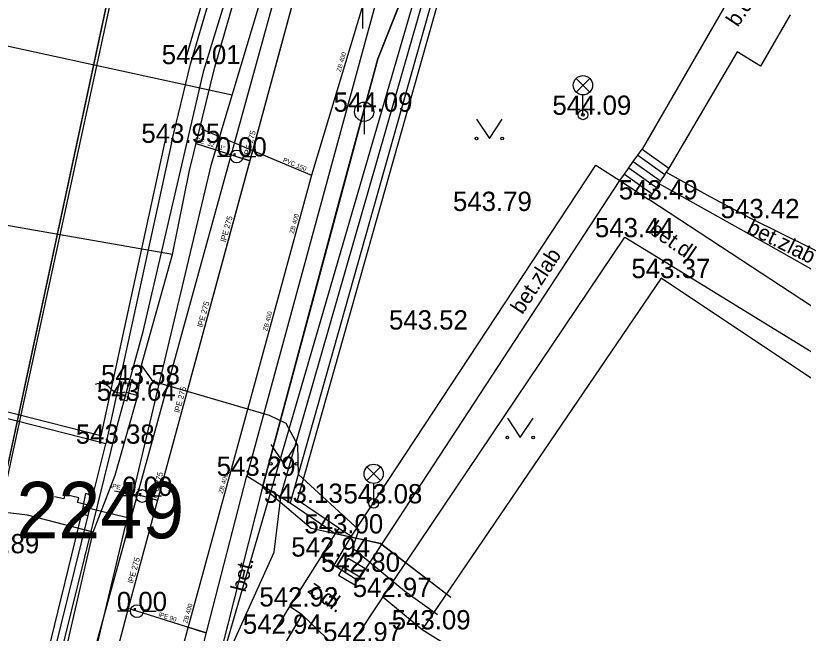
# Model space of a CAD drawing. Extents: x -669393 to -668650, y -1126925 to -1126294.
# Drawn here: x -668961.14 to -668930.51, y -1126607.07 to -1126583.06 of the extents above; entities that cross this region are included whole.
import ezdxf

# ---------------------------------------------------------------- set-up
doc = ezdxf.new("R2010")
doc.units = 0
for name, color, linetype in [('G_Bod_tecka', 7, 'Continuous'), ('G_Bod_vyska', 7, 'Continuous'), ('G_Budovy_Objekty', 7, 'Continuous'), ('G_Cesty_Schody', 7, 'Continuous'), ('G_Objekty_technicke', 7, 'Continuous'), ('G_Plochy_zpevnene', 7, 'Continuous'), ('G_Ploty', 7, 'Continuous'), ('G_Ploty_vstupy', 7, 'Continuous'), ('G_Popisy_povrchu', 7, 'Continuous'), ('G_Site-kanalizace', 7, 'Continuous'), ('G_Site-Rozvadece', 7, 'Continuous'), ('G_Site-vodovod', 7, 'Continuous'), ('G_Z_ELsilove_nadz_kotovane', 7, 'Continuous'), ('G_Z_ELsilove_podz_kotovane', 7, 'Continuous'), ('G_Z_KANAL_podz_kotovane', 7, 'Continuous'), ('G_Z_PLYNY_podz_geodeticky', 7, 'Continuous'), ('G_Z_SPOJE_podz_geodeticky', 7, 'Continuous'), ('G_Z_SPOJE_podz_kotovane', 7, 'Continuous'), ('G_Z_SPOJE_podz_priblizne', 7, 'Continuous'), ('G_Z_SPOJE_podz_zahozene', 7, 'Continuous'), ('G_Z_VODA_podz_kotovane', 7, 'Continuous'), ('G_Zelen-Znacky', 7, 'Continuous'), ('Vrstva 11', 7, 'Continuous'), ('Vrstva 12', 7, 'Continuous'), ('Vrstva 13', 7, 'Continuous'), ('Vrstva 26', 7, 'Continuous'), ('Vrstva 3', 7, 'Continuous'), ('Vrstva 4', 7, 'Continuous'), ('Vrstva 5', 7, 'Continuous'), ('Vrstva 6', 7, 'Continuous')]:
    doc.layers.add(name, color=color, linetype=linetype)

msp = doc.modelspace()

# ---------------------------------------------------------------- linework, layer by layer
at = {"layer": 'G_Bod_tecka'}
for p, q in [((-668954.34, -1126584.94), (-668954.34, -1126584.94)), ((-668947.59, -1126586.79), (-668947.59, -1126586.79)), ((-668939.08, -1126586.91), (-668939.08, -1126586.91)), ((-668955.09, -1126588), (-668955.09, -1126588)), ((-668952.55, -1126588.53), (-668952.55, -1126588.53)), ((-668936.52, -1126590.2), (-668936.52, -1126590.2)), ((-668942.97, -1126590.65), (-668942.97, -1126590.65)), ((-668932.56, -1126590.93), (-668932.56, -1126590.93)), ((-668937.45, -1126591.67), (-668937.45, -1126591.67)), ((-668936.04, -1126593.26), (-668936.04, -1126593.26)), ((-668945.46, -1126595.26), (-668945.46, -1126595.26)), ((-668956.66, -1126597.39), (-668956.66, -1126597.39)), ((-668956.81, -1126598.03), (-668956.81, -1126598.03)), ((-668957.64, -1126599.7), (-668957.64, -1126599.7)), ((-668952.16, -1126600.95), (-668952.16, -1126600.95)), ((-668956.22, -1126601.73), (-668956.22, -1126601.73)), ((-668950.47, -1126602), (-668950.47, -1126602)), ((-668947.22, -1126602.02), (-668947.22, -1126602.02)), ((-668948.72, -1126603.19), (-668948.72, -1126603.19)), ((-668949.26, -1126604.09), (-668949.26, -1126604.09)), ((-668948.08, -1126604.68), (-668948.08, -1126604.68)), ((-668946.87, -1126605.66), (-668946.87, -1126605.66)), ((-668956.43, -1126606.21), (-668956.43, -1126606.21)), ((-668950.5, -1126606.03), (-668950.5, -1126606.03)), ((-668945.33, -1126606.92), (-668945.33, -1126606.92))]:
    msp.add_line(p, q, dxfattribs=at)
at = {"layer": 'G_Budovy_Objekty'}
for p, q in [((-668936.04, -1126593.26), (-668945.33, -1126606.92)), ((-668929.8, -1126597.42), (-668936.04, -1126593.26)), ((-668945.33, -1126606.92), (-668939.39, -1126610.63))]:
    msp.add_line(p, q, dxfattribs=at)
at = {"layer": 'G_Cesty_Schody'}
for p, q in [((-668947.82, -1126605.02), (-668937.65, -1126589.47)), ((-668948.76, -1126604.42), (-668947.82, -1126605.02))]:
    msp.add_line(p, q, dxfattribs=at)
for points in [[(-668937.13, -1126588.73), (-668936.95, -1126588.48)], [(-668936.95, -1126588.48), (-668936.78, -1126588.24)], [(-668936.95, -1126588.48), (-668935.9, -1126589.23)], [(-668936.78, -1126588.24), (-668935.74, -1126588.98)], [(-668937.3, -1126588.97), (-668937.13, -1126588.73)], [(-668937.13, -1126588.73), (-668936.06, -1126589.48)], [(-668937.47, -1126589.22), (-668937.3, -1126588.97)], [(-668937.3, -1126588.97), (-668936.22, -1126589.73)], [(-668935.74, -1126588.98), (-668935.84, -1126589.14)], [(-668937.65, -1126589.47), (-668937.47, -1126589.22)], [(-668937.47, -1126589.22), (-668936.39, -1126589.98)], [(-668935.9, -1126589.23), (-668936.06, -1126589.48)], [(-668935.84, -1126589.14), (-668935.9, -1126589.23)], [(-668937.65, -1126589.47), (-668936.52, -1126590.2)], [(-668936.22, -1126589.73), (-668936.39, -1126589.98)], [(-668936.13, -1126589.58), (-668936.22, -1126589.73)], [(-668936.06, -1126589.48), (-668936.13, -1126589.58)], [(-668936.39, -1126589.98), (-668936.52, -1126590.2)], [(-668946.87, -1126605.66), (-668948.02, -1126607.39)]]:
    msp.add_lwpolyline(points, dxfattribs=at)
at = {"layer": 'G_Objekty_technicke'}
for points in [[(-668939.345, -1126585.495), (-668938.815, -1126586.025)], [(-668939.345, -1126586.025), (-668938.815, -1126585.495)], [(-668939.08, -1126586.91), (-668939.08, -1126586.135)], [(-668947.485, -1126600.605), (-668946.955, -1126601.135)], [(-668947.485, -1126601.135), (-668946.955, -1126600.605)], [(-668947.22, -1126602.02), (-668947.22, -1126601.245)]]:
    msp.add_lwpolyline(points, dxfattribs=at)
for centre, radius in [((-668939.08, -1126585.76), 0.375), ((-668939.08, -1126586.91), 0.19), ((-668939.08, -1126586.91), 0.05), ((-668947.22, -1126600.87), 0.375), ((-668947.22, -1126602.02), 0.19), ((-668947.22, -1126602.02), 0.05)]:
    msp.add_circle(centre, radius, dxfattribs=at)
at = {"layer": 'G_Plochy_zpevnene'}
msp.add_line((-668953.95, -1126607.93), (-668952.16, -1126600.95), dxfattribs=at)
for points in [[(-668959.29, -1126612.12), (-668944.16, -1126557.26)], [(-668934.28, -1126572.28), (-668936.85, -1126571.84), (-668939.43, -1126571.39), (-668939.88, -1126571.34), (-668940.3, -1126571.35), (-668940.71, -1126571.41), (-668941.46, -1126571.62), (-668942.11, -1126571.92), (-668942.65, -1126572.24), (-668943.1, -1126572.57), (-668943.83, -1126573.24), (-668944.31, -1126573.8), (-668944.62, -1126574.24), (-668945, -1126574.93), (-668945.26, -1126575.64), (-668948.71, -1126588.29), (-668952.16, -1126600.95)], [(-668929.46, -1126575.58), (-668936.78, -1126588.24)], [(-668931.02, -1126583.02), (-668932.18, -1126585.02)], [(-668933.08, -1126584.46), (-668935.74, -1126588.98)], [(-668932.18, -1126585.02), (-668933.08, -1126584.46)], [(-668948.08, -1126603.3), (-668938.58, -1126588.87)], [(-668938.58, -1126588.87), (-668937.65, -1126589.47)], [(-668935.84, -1126589.14), (-668934.14, -1126590.09), (-668932.56, -1126590.93), (-668930.2, -1126592.1), (-668929.03, -1126592.7), (-668927.9, -1126593.38)], [(-668936.13, -1126589.58), (-668932.19, -1126591.78), (-668930.23, -1126592.89), (-668928.67, -1126593.82)], [(-668928.98, -1126595.14), (-668936.52, -1126590.2)], [(-668946.87, -1126605.66), (-668937.45, -1126591.67)], [(-668937.45, -1126591.67), (-668936.22, -1126592.42)], [(-668936.22, -1126592.42), (-668929.3, -1126596.67)], [(-668952.16, -1126600.95), (-668950.47, -1126602)], [(-668946.87, -1126605.66), (-668945.33, -1126606.92)], [(-668950, -1126606.35), (-668948.45, -1126607.84), (-668948.35, -1126607.87)]]:
    msp.add_lwpolyline(points, dxfattribs=at)
at = {"layer": 'G_Ploty'}
for p, q in [((-668943.35, -1126576.81), (-668950.47, -1126602)), ((-668950.18, -1126601.9), (-668943.15, -1126577)), ((-668953.45, -1126581.02), (-668954.58, -1126584.87)), ((-668954.34, -1126584.94), (-668953.21, -1126581.09)), ((-668955.34, -1126587.95), (-668957.83, -1126599.39)), ((-668955.09, -1126588), (-668957.64, -1126599.7)), ((-668957.88, -1126599.64), (-668965.58, -1126597.69)), ((-668957.83, -1126599.39), (-668965.53, -1126597.45)), ((-668957.64, -1126599.7), (-668957.88, -1126599.64)), ((-668948.57, -1126602.98), (-668950.18, -1126601.9)), ((-668950.47, -1126602), (-668948.72, -1126603.19)), ((-668958.58, -1126602.43), (-668960.88, -1126611.77)), ((-668960.64, -1126611.83), (-668958.33, -1126602.49)), ((-668948.72, -1126603.19), (-668949.26, -1126604.09)), ((-668948.57, -1126602.98), (-668948.72, -1126603.19)), ((-668948.57, -1126602.98), (-668948.08, -1126603.3)), ((-668948.76, -1126604.42), (-668948.08, -1126603.3)), ((-668949.26, -1126604.09), (-668948.76, -1126604.42)), ((-668950.5, -1126606.03), (-668951.14, -1126607.09)), ((-668950, -1126606.35), (-668950.5, -1126606.03)), ((-668950.63, -1126607.41), (-668950, -1126606.35))]:
    msp.add_line(p, q, dxfattribs=at)
at = {"layer": 'G_Ploty_vstupy'}
for p, q in [((-668955.09, -1126588), (-668954.34, -1126584.94)), ((-668958.14, -1126601.72), (-668957.64, -1126599.7)), ((-668949.26, -1126604.09), (-668950.5, -1126606.03))]:
    msp.add_line(p, q, dxfattribs=at)
at = {"layer": 'G_Site-kanalizace'}
for points in [[(-668947.66, -1126582.305), (-668947.66, -1126583.555)], [(-668947.59, -1126586.415), (-668947.59, -1126587.665)], [(-668948.403, -1126604.489), (-668947.757, -1126604.871)]]:
    msp.add_lwpolyline(points, dxfattribs=at)
msp.add_lwpolyline([(-668948.593, -1126604.811), (-668947.947, -1126605.193), (-668947.566, -1126604.547), (-668948.212, -1126604.166)], close=True, dxfattribs=at)
msp.add_circle((-668947.59, -1126586.79), 0.375, dxfattribs=at)
at = {"layer": 'G_Site-Rozvadece'}
for points in [[(-668956.95, -1126597.32), (-668957.1, -1126597.96), (-668956.81, -1126598.03), (-668956.66, -1126597.39)], [(-668958.43, -1126601.64), (-668958.58, -1126602.43), (-668958.33, -1126602.49), (-668958.14, -1126601.72)]]:
    msp.add_lwpolyline(points, close=True, dxfattribs=at)
msp.add_lwpolyline([(-668958.38, -1126602.071), (-668958.737, -1126601.981), (-668958.693, -1126601.803), (-668959.229, -1126601.671), (-668959.274, -1126601.849), (-668959.631, -1126601.761)], dxfattribs=at)
for centre, start, end in [((-668957.848, -1126597.86), 39.7092, 113.449), ((-668957.079, -1126597.221), 219.7092, 293.449)]:
    msp.add_arc(centre, 0.5, start, end, dxfattribs=at)
at = {"layer": 'G_Site-vodovod'}
for points in [[(-668952.8, -1126588.53), (-668953.3, -1126588.53)], [(-668952.3, -1126588.53), (-668951.8, -1126588.53)], [(-668956.47, -1126601.73), (-668956.97, -1126601.73)], [(-668955.97, -1126601.73), (-668955.47, -1126601.73)], [(-668956.68, -1126606.21), (-668957.18, -1126606.21)], [(-668956.18, -1126606.21), (-668955.68, -1126606.21)]]:
    msp.add_lwpolyline(points, dxfattribs=at)
for centre in [(-668952.55, -1126588.53), (-668956.22, -1126601.73), (-668956.43, -1126606.21)]:
    msp.add_circle(centre, 0.25, dxfattribs=at)
at = {"layer": 'G_Z_ELsilove_nadz_kotovane'}
msp.add_lwpolyline([(-668969.82, -1126641.84), (-668962.08, -1126603.84), (-668954.82, -1126570.41), (-668947.579, -1126533.09)], dxfattribs=at)
at = {"layer": 'G_Z_ELsilove_podz_kotovane'}
msp.add_lwpolyline([(-668986.81, -1126790.89), (-668983.74, -1126752.7), (-668981.4, -1126714.88), (-668976.88, -1126675.24), (-668969.5, -1126644.98), (-668962.32, -1126604.58), (-668954.59, -1126568.6), (-668939.06, -1126504.37)], dxfattribs=at)
at = {"layer": 'G_Z_KANAL_podz_kotovane'}
msp.add_line((-668953.93, -1126587.46), (-668949.64, -1126589.26), dxfattribs=at)
msp.add_lwpolyline([(-668947.66, -1126582.68), (-668949.64, -1126589.26), (-668954.51, -1126607.11), (-668957.21, -1126617.22), (-668960.66, -1126630.26)], dxfattribs=at)
at = {"layer": 'G_Z_PLYNY_podz_geodeticky'}
for points in [[(-668972.663, -1126674.589), (-668970.71, -1126662.16), (-668970.45, -1126660.58), (-668967.39, -1126647.2), (-668966.76, -1126644.42), (-668965.71, -1126640.04), (-668961.7, -1126623.19), (-668956.8, -1126602.57), (-668953.53, -1126588.83), (-668952.72, -1126586.15), (-668946.84, -1126566.52), (-668945.79, -1126563), (-668931.12, -1126514.78), (-668929.96, -1126511.12), (-668931.66, -1126510.6), (-668931.41, -1126509.79)], [(-668952.72, -1126586.15), (-668962.75, -1126583.97), (-668969.51, -1126582.88), (-668969.7, -1126584.58)], [(-668958.5, -1126602.16), (-668956.8, -1126602.57)]]:
    msp.add_lwpolyline(points, dxfattribs=at)
at = {"layer": 'G_Z_SPOJE_podz_geodeticky'}
for points in [[(-668965.71, -1126659.23), (-668961.42, -1126636.58), (-668943.94, -1126576.61), (-668934.24, -1126554.95), (-668916.63, -1126516.53), (-668915.06, -1126512.35), (-668913.11, -1126502.62)], [(-668955.05, -1126592.34), (-668954.38, -1126589.07), (-668953.4, -1126585.06), (-668948.63, -1126568.5)], [(-668955.05, -1126592.34), (-668964.02, -1126590.77), (-668964.1, -1126590.75)], [(-668956.25, -1126596.64), (-668955.05, -1126592.34)], [(-668956.39, -1126597.83), (-668956.25, -1126596.64)], [(-668947.8, -1126603.05), (-668950.14, -1126600.9), (-668950.17, -1126599.75), (-668950.63, -1126598.92), (-668951.27, -1126598.6), (-668955.8, -1126597.28), (-668956.25, -1126596.64)], [(-668958.13, -1126603.14), (-668957.28, -1126600.92), (-668956.39, -1126597.83)], [(-668956.86, -1126597.7), (-668956.39, -1126597.83)], [(-668958.13, -1126603.14), (-668960.68, -1126602.48), (-668961.79, -1126602.35), (-668964.35, -1126601.86), (-668966.04, -1126600.32)], [(-668963.72, -1126626.54), (-668961.18, -1126616.81), (-668960, -1126611.24), (-668958.13, -1126603.14)], [(-668947.8, -1126603.05), (-668948.04, -1126603.75), (-668946.02, -1126605.42), (-668944.74, -1126606.34)]]:
    msp.add_lwpolyline(points, dxfattribs=at)
at = {"layer": 'G_Z_SPOJE_podz_kotovane'}
for points in [[(-668974.36, -1126674.07), (-668973.06, -1126668.98), (-668971.96, -1126664.36), (-668970.68, -1126658.03), (-668969.3, -1126650.34), (-668968.2, -1126645.42), (-668967.12, -1126640.35), (-668966.32, -1126638.27), (-668965.98, -1126636.58), (-668964.19, -1126628.16), (-668961.63, -1126617.34), (-668960.75, -1126613.4), (-668957.18, -1126598.96), (-668956.18, -1126595.34), (-668953.83, -1126585.18), (-668949.97, -1126572.67), (-668944.82, -1126555.69), (-668942.42, -1126548.43), (-668938.93, -1126537.21), (-668934.92, -1126523.88)], [(-668967.21, -1126674.78), (-668966.11, -1126667.11), (-668964.1, -1126654.97), (-668963.7, -1126653.53), (-668962.9, -1126653.19), (-668960.93, -1126641.59), (-668958.61, -1126631.73), (-668954.53, -1126631.88), (-668949.06, -1126611.36), (-668952.94, -1126608.03), (-668951.09, -1126603.92), (-668950.82, -1126601.67), (-668943.9, -1126577.58), (-668943.62, -1126576.63), (-668939.63, -1126575.42), (-668938.77, -1126574.92), (-668937.37, -1126573.94), (-668936.3, -1126571.54), (-668934.65, -1126567.91), (-668933.72, -1126566.17), (-668932.96, -1126564.96)], [(-668955.05, -1126592.34), (-668954.38, -1126589.07), (-668953.4, -1126585.06), (-668948.63, -1126568.5)], [(-668955.05, -1126592.34), (-668964.02, -1126590.77), (-668964.1, -1126590.75)], [(-668956.25, -1126596.64), (-668955.05, -1126592.34)], [(-668956.39, -1126597.83), (-668956.25, -1126596.64)], [(-668947.8, -1126603.05), (-668950.14, -1126600.9), (-668950.17, -1126599.75), (-668950.63, -1126598.92), (-668951.27, -1126598.6), (-668955.8, -1126597.28), (-668956.25, -1126596.64)], [(-668958.13, -1126603.14), (-668957.28, -1126600.92), (-668956.39, -1126597.83)], [(-668956.86, -1126597.7), (-668956.39, -1126597.83)], [(-668958.13, -1126603.14), (-668960.68, -1126602.48), (-668961.79, -1126602.35), (-668964.35, -1126601.86), (-668966.04, -1126600.32)], [(-668963.72, -1126626.54), (-668961.18, -1126616.81), (-668960, -1126611.24), (-668958.13, -1126603.14)], [(-668947.8, -1126603.05), (-668948.04, -1126603.75), (-668946.02, -1126605.42), (-668944.74, -1126606.34)]]:
    msp.add_lwpolyline(points, dxfattribs=at)
at = {"layer": 'G_Z_SPOJE_podz_priblizne'}
for points in [[(-668965.71, -1126659.23), (-668961.42, -1126636.58), (-668943.94, -1126576.61), (-668934.24, -1126554.95), (-668916.63, -1126516.53), (-668915.06, -1126512.35), (-668913.11, -1126502.62)], [(-668955.05, -1126592.34), (-668954.38, -1126589.07), (-668953.4, -1126585.06), (-668948.63, -1126568.5)], [(-668955.05, -1126592.34), (-668964.02, -1126590.77), (-668964.1, -1126590.75)], [(-668956.25, -1126596.64), (-668955.05, -1126592.34)], [(-668956.39, -1126597.83), (-668956.25, -1126596.64)], [(-668947.8, -1126603.05), (-668950.14, -1126600.9), (-668950.17, -1126599.75), (-668950.63, -1126598.92), (-668951.27, -1126598.6), (-668955.8, -1126597.28), (-668956.25, -1126596.64)], [(-668958.13, -1126603.14), (-668957.28, -1126600.92), (-668956.39, -1126597.83)], [(-668956.86, -1126597.7), (-668956.39, -1126597.83)], [(-668958.13, -1126603.14), (-668960.68, -1126602.48), (-668961.79, -1126602.35), (-668964.35, -1126601.86), (-668966.04, -1126600.32)], [(-668963.72, -1126626.54), (-668961.18, -1126616.81), (-668960, -1126611.24), (-668958.13, -1126603.14)], [(-668947.8, -1126603.05), (-668948.04, -1126603.75), (-668946.02, -1126605.42), (-668944.74, -1126606.34)]]:
    msp.add_lwpolyline(points, dxfattribs=at)
at = {"layer": 'G_Z_SPOJE_podz_zahozene'}
for p, q in [((-668947.06, -1126584.73), (-668936.79, -1126558.94)), ((-668948.66, -1126590.66), (-668947.06, -1126584.73)), ((-668951.55, -1126601.39), (-668948.66, -1126590.66)), ((-668951.55, -1126601.39), (-668954.92, -1126614.72)), ((-668949.65, -1126603), (-668951.55, -1126601.39)), ((-668946.95, -1126603.59), (-668949.65, -1126603)), ((-668944.22, -1126605.68), (-668946.95, -1126603.59))]:
    msp.add_line(p, q, dxfattribs=at)
at = {"layer": 'G_Z_VODA_podz_kotovane'}
for points in [[(-668911.63, -1126458.38), (-668911.94, -1126472.87), (-668917.84, -1126504.71), (-668919.43, -1126508.14), (-668925.09, -1126520.35), (-668931.13, -1126532.07), (-668941.27, -1126553.58), (-668941.86, -1126555.28), (-668944.85, -1126563.31), (-668947.04, -1126570.29), (-668952.04, -1126588.69), (-668955.63, -1126601.9), (-668956.77, -1126606.11), (-668961.43, -1126623.79), (-668964.55, -1126637.99), (-668966, -1126644.81), (-668969.29, -1126661.42), (-668971.68, -1126675.88)], [(-668954.16, -1126588.01), (-668952.55, -1126588.53), (-668952.04, -1126588.69)], [(-668957.3, -1126601.53), (-668956.22, -1126601.73), (-668955.63, -1126601.9)], [(-668953.73, -1126607.06), (-668954.79, -1126606.73), (-668956.43, -1126606.21), (-668956.77, -1126606.11)]]:
    msp.add_lwpolyline(points, dxfattribs=at)
at = {"layer": 'G_Zelen-Znacky'}
for points in [[(-668943.22, -1126587.08), (-668942.72, -1126587.83)], [(-668942.72, -1126587.83), (-668942.22, -1126587.08)], [(-668942.02, -1126598.71), (-668941.52, -1126599.46)], [(-668941.52, -1126599.46), (-668941.02, -1126598.71)], [(-668951.22, -1126599.73), (-668950.72, -1126600.48)], [(-668950.72, -1126600.48), (-668950.22, -1126599.73)]]:
    msp.add_lwpolyline(points, dxfattribs=at)
for centre in [(-668943.22, -1126587.83), (-668942.22, -1126587.83), (-668942.02, -1126599.46), (-668941.02, -1126599.46), (-668951.22, -1126600.48), (-668950.22, -1126600.48)]:
    msp.add_circle(centre, 0.05, dxfattribs=at)
at = {"layer": 'Vrstva 11'}
for points in [[(-668928.464, -1126509.545), (-668930.126, -1126515.891), (-668931.768, -1126520.514), (-668921.6, -1126524.127), (-668925.153, -1126532.268), (-668936.793, -1126558.936), (-668947.061, -1126584.729), (-668948.658, -1126590.658), (-668951.548, -1126601.392), (-668954.915, -1126614.718), (-668959.645, -1126633.436), (-668961.508, -1126641.36), (-668963.676, -1126652.148), (-668963.8, -1126654.117), (-668964.163, -1126659.861), (-668964.494, -1126665.114), (-668965.444, -1126668.273), (-668966.205, -1126676.085)], [(-668951.548, -1126601.392), (-668948.658, -1126590.658), (-668947.061, -1126584.729), (-668936.793, -1126558.936), (-668925.153, -1126532.268), (-668921.6, -1126524.127), (-668919.327, -1126524.437), (-668915.311, -1126525.848), (-668896.577, -1126530.077)], [(-668951.548, -1126601.392), (-668954.915, -1126614.718), (-668959.645, -1126633.436), (-668961.508, -1126641.36), (-668963.676, -1126652.148), (-668963.8, -1126654.117), (-668964.163, -1126659.861), (-668964.494, -1126665.114), (-668965.444, -1126668.273), (-668966.205, -1126676.085)], [(-668944.222, -1126605.676), (-668946.954, -1126603.586), (-668949.647, -1126603.001), (-668951.548, -1126601.392), (-668954.915, -1126614.718), (-668959.645, -1126633.436), (-668961.508, -1126641.36), (-668963.676, -1126652.148), (-668963.8, -1126654.117), (-668964.163, -1126659.861), (-668964.494, -1126665.114), (-668965.444, -1126668.273), (-668966.205, -1126676.085)]]:
    msp.add_lwpolyline(points, dxfattribs=at)
at = {"layer": 'Vrstva 12'}
msp.add_lwpolyline([(-668947.658, -1126582.682), (-668949.635, -1126589.262), (-668954.51, -1126607.11), (-668957.209, -1126617.216), (-668960.657, -1126630.265)], dxfattribs=at)
at = {"layer": 'Vrstva 13'}
msp.add_line((-668953.93, -1126587.46), (-668949.635, -1126589.262), dxfattribs=at)
at = {"layer": 'Vrstva 26'}
for points in [[(-668911.629, -1126458.384), (-668911.94, -1126472.871), (-668917.84, -1126504.71), (-668919.428, -1126508.136), (-668925.09, -1126520.35), (-668931.13, -1126532.07), (-668941.27, -1126553.58), (-668941.858, -1126555.282), (-668944.85, -1126563.31), (-668947.04, -1126570.29), (-668952.039, -1126588.693), (-668955.626, -1126601.898), (-668956.767, -1126606.112), (-668961.43, -1126623.79), (-668964.551, -1126637.993), (-668965.997, -1126644.809), (-668969.289, -1126661.422), (-668971.679, -1126675.884)], [(-668954.16, -1126588.01), (-668952.55, -1126588.53), (-668952.039, -1126588.693)], [(-668957.3, -1126601.53), (-668956.22, -1126601.73), (-668955.626, -1126601.898)], [(-668953.729, -1126607.061), (-668954.787, -1126606.728), (-668956.43, -1126606.21), (-668956.767, -1126606.112)]]:
    msp.add_lwpolyline(points, dxfattribs=at)
at = {"layer": 'Vrstva 5'}
msp.add_line((-668962.32, -1126604.58), (-668954.59, -1126568.6), dxfattribs=at)
at = {"layer": 'Vrstva 6'}
for p, q in [((-668952.55, -1126588.53), (-668952.55, -1126588.53)), ((-668956.22, -1126601.73), (-668956.22, -1126601.73)), ((-668956.43, -1126606.21), (-668956.43, -1126606.21))]:
    msp.add_line(p, q, dxfattribs=at)

# ---------------------------------------------------------------- texts
at = {"layer": 'G_Bod_vyska'}
for s, p in [('544.01', (-668955.464, -1126584.94)), ('544.09', (-668948.778, -1126586.79)), ('544.09', (-668940.268, -1126586.91)), ('543.95', (-668956.256, -1126588)), ('0.00', (-668953.33, -1126588.53)), ('543.49', (-668937.686, -1126590.2)), ('543.79', (-668944.136, -1126590.65)), ('543.42', (-668933.724, -1126590.93)), ('543.44', (-668938.614, -1126591.67)), ('543.37', (-668937.194, -1126593.26)), ('543.52', (-668946.624, -1126595.26)), ('543.58', (-668957.824, -1126597.39)), ('543.64', (-668957.988, -1126598.03)), ('543.38', (-668958.804, -1126599.7)), ('543.29', (-668953.326, -1126600.95)), ('0.00', (-668957, -1126601.73)), ('543.13', (-668951.49, -1126602)), ('543.08', (-668948.396, -1126602.02)), ('543.00', (-668949.917, -1126603.19)), ('543.89', (-668963.296, -1126603.96)), ('542.94', (-668950.426, -1126604.09)), ('542.80', (-668949.266, -1126604.68)), ('542.97', (-668948.036, -1126605.66)), ('542.93', (-668951.666, -1126606.03)), ('0.00', (-668957.21, -1126606.21)), ('543.09', (-668946.518, -1126606.92)), ('542.94', (-668952.306, -1126607.09)), ('542.97', (-668949.186, -1126607.39))]:
    msp.add_text(s, height=0.75, dxfattribs=at).set_placement(p)
at = {"layer": 'G_Popisy_povrchu'}
for s, rotation, p in [('b.dl.', 56.1089, (-668933.057, -1126583.527)), ('bet.zlab', 333.7567, (-668932.743, -1126591.478)), ('bet.dl.', 325.1658, (-668936.565, -1126591.475)), ('bet.zlab', 56.8216, (-668941.437, -1126594.703)), ('bet.', 75.6208, (-668952.208, -1126605.497)), ('z.dl.', 324.6571, (-668949.834, -1126605.453))]:
    msp.add_text(s, height=0.6, rotation=rotation, dxfattribs=at).set_placement(p)
at = {"layer": 'Vrstva 3'}
for s, rotation, p in [('ZB 400', 73.3357, (-668948.505, -1126585.253)), ('PVC 150', 337.2521, (-668950.769, -1126588.73)), ('ZB 400', 74.7235, (-668950.331, -1126591.541)), ('ZB 400', 74.8019, (-668951.366, -1126595.333)), ('ZB 400', 74.7627, (-668953.091, -1126601.648)), ('ZB 400', 74.7235, (-668954.47, -1126606.699))]:
    msp.add_text(s, height=0.1755, rotation=rotation, dxfattribs=at).set_placement(p)
at = {"layer": 'Vrstva 4'}
for s, height, rotation, p in [('lPE 275', 0.2194, 74.761, (-668952.071, -1126588.548)), ('lPE  32 - 1"', 0.17551, 342.2348, (-668954.189, -1126587.937)), ('lPE 275', 0.2194, 74.761, (-668952.972, -1126591.868)), ('lPE 275', 0.2194, 74.761, (-668953.874, -1126595.188)), ('lPE 275', 0.2194, 74.761, (-668954.775, -1126598.507)), ('lPE 275', 0.2194, 74.761, (-668955.676, -1126601.827)), ('lPE  32 - 1"', 0.17551, 348.413, (-668957.454, -1126601.413)), ('lPE 275', 0.2194, 74.761, (-668956.578, -1126605.146)), ('lPE 90', 0.1755, 342.613, (-668955.6, -1126606.412))]:
    msp.add_text(s, height=height, rotation=rotation, dxfattribs=at).set_placement(p)
msp.add_text('2249', height=2.1939, dxfattribs=at).set_placement((-668961.117, -1126603.378))

doc.saveas('drawing.dxf')
